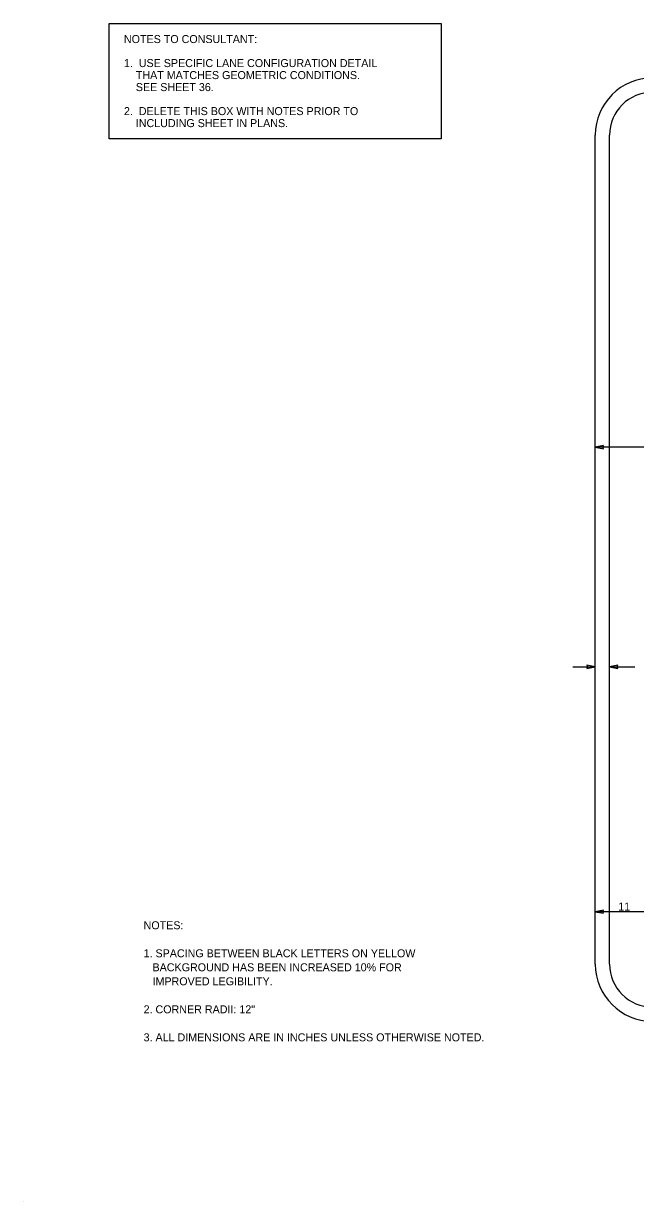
# Model space of a CAD drawing. Extents: x 319701 to 320014, y 1621790 to 1621996.
# Drawn here: x 319700.6 to 319807.6, y 1621790 to 1621996 of the extents above; entities that cross this region are included whole.
import ezdxf

# ---------------------------------------------------------------- set-up
doc = ezdxf.new("R2010")
doc.units = 0
for name, color, linetype in [('1', 7, 'Continuous'), ('48', 7, 'Continuous'), ('52', 7, 'Continuous'), ('AdhocPoint_dp', 7, 'Continuous'), ('TextAlert', 7, 'Continuous'), ('TextNotes', 7, 'Continuous')]:
    doc.layers.add(name, color=color, linetype=linetype)

msp = doc.modelspace()

# ---------------------------------------------------------------- linework, layer by layer
at = {"layer": '1'}
for p, q in [((319800.55, 1621831.54), (319800.55, 1621976.54)), ((319803.05, 1621831.54), (319803.05, 1621976.54))]:
    msp.add_line(p, q, dxfattribs=at)
for centre, radius, start, end in [((319810.55, 1621976.54), 10, 90, 180), ((319810.55, 1621976.54), 7.5, 90, 180), ((319810.55, 1621831.54), 10, 180, 270), ((319810.55, 1621831.54), 7.5, 180, 270)]:
    msp.add_arc(centre, radius, start, end, dxfattribs=at)
at = {"layer": '48'}
for p, q in [((319825.14, 1621921.96), (319800.55, 1621921.96)), ((319796.63, 1621883.55), (319800.55, 1621883.55)), ((319803.05, 1621883.55), (319807.44, 1621883.55)), ((319809.72, 1621840.71), (319800.55, 1621840.71))]:
    msp.add_line(p, q, dxfattribs=at)
at = {"layer": '52'}
for p, q in [((319802, 1621922.23), (319800.55, 1621921.96)), ((319800.55, 1621921.96), (319802, 1621921.68)), ((319801.89, 1621921.96), (319802, 1621922.23)), ((319802, 1621921.68), (319801.89, 1621921.96)), ((319800.55, 1621883.54), (319799.1, 1621883.82)), ((319799.1, 1621883.82), (319799.21, 1621883.54)), ((319799.21, 1621883.54), (319799.1, 1621883.27)), ((319799.1, 1621883.27), (319800.55, 1621883.54)), ((319804.5, 1621883.81), (319803.05, 1621883.54)), ((319803.05, 1621883.54), (319804.5, 1621883.26)), ((319804.39, 1621883.54), (319804.5, 1621883.81)), ((319804.5, 1621883.26), (319804.39, 1621883.54)), ((319802, 1621840.98), (319800.55, 1621840.71)), ((319800.55, 1621840.71), (319802, 1621840.43)), ((319801.89, 1621840.71), (319802, 1621840.98)), ((319802, 1621840.43), (319801.89, 1621840.71))]:
    msp.add_line(p, q, dxfattribs=at)
at = {"layer": 'AdhocPoint_dp'}
msp.add_line((319700.55, 1621790.04), (319700.55, 1621790.04), dxfattribs=at)
at = {"layer": 'TextAlert'}
msp.add_lwpolyline([(319715.55, 1621996.04), (319773.58, 1621996.04), (319773.58, 1621975.87), (319715.55, 1621975.87)], close=True, dxfattribs=at)

# ---------------------------------------------------------------- texts
at = {"layer": '48'}
msp.add_text('11', height=1.4, dxfattribs=at).set_placement((319804.56, 1621840.92))
at = {"layer": 'TextAlert'}
for s, p in [('NOTES TO CONSULTANT:', (319718.11, 1621992.63)), ('1.  USE SPECIFIC LANE CONFIGURATION DETAIL', (319718.11, 1621988.43)), ('    THAT MATCHES GEOMETRIC CONDITIONS. ', (319718.11, 1621986.33)), ('    SEE SHEET 36.', (319718.11, 1621984.23)), ('2.  DELETE THIS BOX WITH NOTES PRIOR TO ', (319718.11, 1621980.03)), ('    INCLUDING SHEET IN PLANS.', (319718.11, 1621977.93))]:
    msp.add_text(s, height=1.4, dxfattribs=at).set_placement(p)
at = {"layer": 'TextNotes'}
for s, p in [('NOTES:', (319721.55, 1621837.64)), ('1. SPACING BETWEEN BLACK LETTERS ON YELLOW', (319721.55, 1621832.74)), ('   BACKGROUND HAS BEEN INCREASED 10% FOR', (319721.55, 1621830.29)), ('   IMPROVED LEGIBILITY.', (319721.55, 1621827.84)), ('2. CORNER RADII: 12"', (319721.55, 1621822.94)), ('3. ALL DIMENSIONS ARE IN INCHES UNLESS OTHERWISE NOTED.', (319721.55, 1621818.04))]:
    msp.add_text(s, height=1.4, dxfattribs=at).set_placement(p)

doc.saveas('drawing.dxf')
